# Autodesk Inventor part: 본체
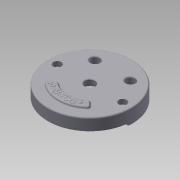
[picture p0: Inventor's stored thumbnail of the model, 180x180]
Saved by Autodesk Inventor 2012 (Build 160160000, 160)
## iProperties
Created: 2015-04
Part Number: 본체
Material: 알루미늄-6061
Document SubType Name: Modeling
Designer: Administrator
Density: 2.71 g/cm^3
Mass: 1051.94 g
Surface Area: 1006.91 cm^2
Volume: 388.169 cm^3
Author: Administrator
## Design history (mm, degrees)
sketch "스케치1"
  geometry: C1 r 95 at (0, 0); 1 further point
  constraints: 1 centre point, 1 coincident
  dimensions: "d0" = 190 diameter of C1
extrude "돌출1" new body sketch "스케치1" distance "d1" = 32; taper "d2" = 0 deg
sketch "스케치2"
  geometry: C1 r 95 at (0, 0) reference; C2 r 90 at (0, 0)
  constraints: 1 centre point, 1 coincident
  dimensions: "d3" = 180 diameter of C2
extrude "돌출2" cut sketch "스케치2" distance "d4" = 25; taper "d5" = 0 deg
sketch "스케치3"
  geometry: L1 (-40.249, 12)-(-89.196, 12); L2 (40.249, 12)-(89.196, 12); A1 r 90 centre (0, 0) between (-89.196, 12) and (89.196, 12) reference; A2 r 42 centre (0, 0) between (40.249, 12) and (-40.249, 12)
  constraints: 4 end point, 4 point on circle, 1 centre point, 1 coincident, 1 collinear
extrude "돌출3" join sketch "스케치3" distance "d8" = 7; taper "d9" = 0 deg
sketch "스케치4"
  geometry: L1 (-95, 32)-(95, 32) reference; L2 (-95, 0)-(95, 0) reference; L3 (12, 18)-(-90, 18) reference; L4 (0, 18)-(0, 8); L5 (0, 18)-(35, 18); L6 (0, 8)-(33.237, 8); L7 (35, 18)-(33.237, 8); 1 further point
  constraints: 8 end point, 2 perpendicular, 1 parallel, 1 point on line
revolve "회전1" sketch "스케치4" stored, may be unused: angle "d14" = 90 deg
sketch "스케치5"
  geometry: L1 (-89.658, -7.844)-(-94.638, -8.28); L2 (89.658, -7.844)-(94.638, -8.28); C1 r 90 at (0, 0) reference; C2 r 95 at (0, 0) reference; A1 r 90 centre (0, 0) between (-89.658, -7.844) and (89.658, -7.844); A2 r 95 centre (0, 0) between (-94.638, -8.28) and (94.638, -8.28)
  constraints: 4 end point, 4 point on circle, 2 centre point, 2 coincident, 2 concentric
extrude "돌출4" cut sketch "스케치5" distance "d17" = 5; taper "d18" = 0 deg
sketch "스케치6"
  geometry: C1 r 15 at (-40, 52); C2 r 15 at (40, 52)
  constraints: 2 centre point
extrude "돌출5" join sketch "스케치6" distance "d24" = 25; taper "d25" = 0 deg
sketch "스케치8"
  geometry: L1 (0, -19)-(0, -14); L2 (59, -19)-(59, -14); L3 (41, -19)-(41, -14); L4 (-41, -19)-(-41, -14); L5 (-59, -19)-(-59, -14); A1 r 59 centre (0, -19) between (-59, -19) and (59, -19); A2 r 41 centre (0, -19) between (-41, -19) and (41, -19); A3 r 9 centre (-50, -14) between (-41, -14) and (-59, -14); A4 r 9 centre (50, -14) between (59, -14) and (41, -14)
  constraints: 10 end point, 8 point on circle, 4 centre point, 4 tangent, 2 parallel, 1 coincident
extrude "돌출7" cut sketch "스케치8" distance "d41" = 7; taper "d42" = 0 deg
sketch "스케치9"
  geometry: C1 r 15 at (0, 0) reference; C2 r 10 at (0, 0); C3 r 15 at (80, 0) reference; C4 r 10 at (80, 0); 1 further point
  constraints: 2 centre point, 2 coincident
  dimensions: "d43" = 20 diameter of C2
extrude "돌출8" cut sketch "스케치9" distance "d45" = 50; taper "d46" = 0 deg
sketch "스케치10"
  geometry: C1 r 33.237 at (0, 0) reference; C2 r 25 at (0, 0)
  constraints: 1 centre point, 1 coincident
  dimensions: "d47" = 50 diameter of C2
extrude "돌출9" cut sketch "스케치10" distance "d48" = 15; taper "d49" = 0 deg
sketch "스케치11"
  geometry: C1 r 25 at (0, 0) reference; C2 r 11.5 at (0, 0)
  constraints: 1 centre point, 1 coincident
  dimensions: "d50" = 23 diameter of C2
extrude "돌출10" cut sketch "스케치11" distance "d51" = 20; taper "d52" = 0 deg
sketch "스케치13"
  geometry: L1 (-80, 0)-(-74, 0); L2 (-74, 8)-(-74, 13.748); L3 (-80, 0)-(-86, 0); L4 (-86, 8)-(-86, 13.748); L5 (-74, -8)-(-74, -13.748); L6 (-86, -8)-(-86, -13.748); A1 r 10 centre (-80, 0) between (-86, 8) and (-74, 8) reference; A2 r 15 centre (-80, 0) between (-86, -13.748) and (-74, -13.748) reference; 1 further point
  constraints: 12 end point, 8 point on circle, 3 perpendicular, 2 parallel, 1 horizontal
extrude "돌출12" cut sketch "스케치13" distance "d60" = 3; taper "d61" = 0 deg
sketch "스케치14"
  geometry: L1 (8, 6)-(13.748, 6); L2 (-8, 6)-(-13.748, 6); L3 (8, -6)-(13.748, -6); L4 (-8, -6)-(-13.748, -6); A1 r 10 centre (0, 0) between (-8, 6) and (8, 6) reference; A2 r 15 centre (0, 0) between (-13.748, -6) and (-13.748, 6) reference; 1 further point
  constraints: 8 end point, 8 point on circle, 2 collinear
extrude "돌출13" cut sketch "스케치14" distance "d64" = 3; taper "d65" = 0 deg
sketch "스케치15"
  geometry: L1 (-36.062, -36.062)-(-50.912, -50.912); L2 (36.062, -36.062)-(50.912, -50.912); C1 r 95 at (0, 0) reference; A1 r 51 centre (0, 0) between (-36.062, -36.062) and (36.062, -36.062); A2 r 72 centre (0, 0) between (-50.912, -50.912) and (50.912, -50.912)
  constraints: 4 end point, 4 point on circle, 2 centre point, 2 coincident
extrude "돌출14" join sketch "스케치15" distance "d70" = 5; taper "d71" = 0 deg
sketch "스케치16"
  geometry: L1 (-50.912, -50.912)-(-36.062, -36.062) reference; L2 (36.062, -36.062)-(50.912, -50.912) reference; A1 r 72 centre (0, 0) between (-50.912, -50.912) and (50.912, -50.912) reference; A2 r 68 centre (0, 0) between (-48.083, -48.083) and (48.083, -48.083)
  constraints: 2 point on circle, 2 point on line, 1 centre point, 1 coincident, 1 other
feature "엠보싱1" sketch "스케치16" dims "d1" = 32, "d2" = 0, "d75" = 0.5, "d76" = 0
fillet "모깎기1" dims "d79" = 10, "d80" = 0.3, "d81" = 3, "d83" = 1
chamfer "모따기1" distance "d95" = 1; stored, may be unused: second distance "d96" = 2, angle "d97" = 45 deg
sketch "스케치17"
  geometry: C1 r 9 at (-74, 0)
  constraints: 1 centre point
  dimensions: "d101" = 18 diameter of C1
extrude "돌출15" join sketch "스케치17" distance "d102" = 18; taper "d103" = 0 deg
sketch "스케치18"
  geometry: C1 r 9 at (0, 0) reference; C2 r 5.5 at (0, 0); 1 further point
  constraints: 1 centre point, 1 coincident
  dimensions: "d104" = 11 diameter of C2
extrude "돌출16" cut sketch "스케치18" stored distance "d105" = 18; taper "d106" = 0 deg
sketch "스케치19"
  geometry: C1 r 5.5 at (74, 0) reference; C2 r 9 at (74, 0)
  constraints: 1 centre point, 1 coincident
  dimensions: "d107" = 18 diameter of C2
extrude "돌출17" cut sketch "스케치19" distance "d108" = 11; taper "d109" = 0 deg
node "솔리드1"
fillet "모깎기2" dims "d91" = 5, "d93" = 3
fillet "모깎기3" dims "d92" = 3, "d94" = 2
mirror "대칭1"
node "투영된 루프1"
node "투영된 루프2"
node "투영된 루프4"
